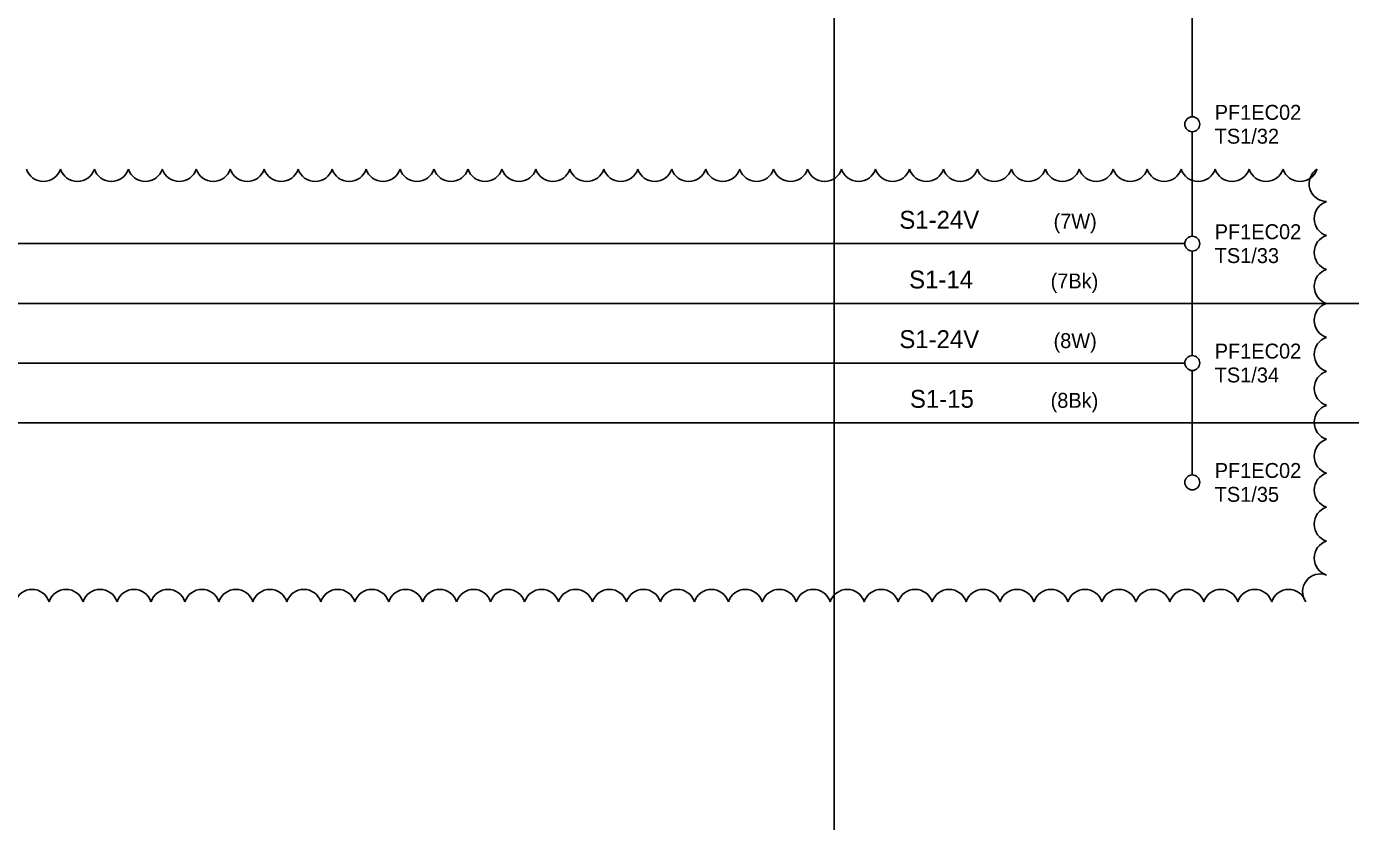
# Model space of a CAD drawing. Extents: x 0 to 841, y 0 to 594.
# Drawn here: x 414.7 to 636.5, y 133.2 to 266.4 of the extents above; entities that cross this region are included whole.
import ezdxf

# ---------------------------------------------------------------- set-up
doc = ezdxf.new("R2010")
doc.units = 0
for name, color, linetype in [('Level 1', 7, 'Continuous'), ('Level 10', 7, 'Continuous'), ('Level 2', 7, 'Continuous')]:
    doc.layers.add(name, color=color, linetype=linetype)

msp = doc.modelspace()

# ---------------------------------------------------------------- linework, layer by layer
at = {"layer": 'Level 1'}
for p, q in [((550, 572.5), (550, 57)), ((610, 251.25), (610, 268.75)), ((610, 231.25), (610, 248.75)), ((270, 230), (608.75, 230)), ((610, 211.25), (610, 228.75)), ((270, 220), (685, 220)), ((270, 210), (608.75, 210)), ((610, 191.25), (610, 208.75)), ((270, 200), (685, 200))]:
    msp.add_line(p, q, dxfattribs=at)
for centre, start, end in [((417.58, 243.4), 197.5, 342.5), ((423.27, 243.4), 197.5, 342.5), ((428.96, 243.4), 197.5, 342.5), ((434.65, 243.4), 197.5, 342.5), ((440.33, 243.4), 197.5, 342.5), ((446.02, 243.4), 197.5, 342.5), ((451.71, 243.4), 197.5, 342.5), ((457.4, 243.4), 197.5, 342.5), ((463.09, 243.4), 197.5, 342.5), ((468.78, 243.4), 197.5, 342.5), ((474.46, 243.4), 197.5, 342.5), ((480.15, 243.4), 197.5, 342.5), ((485.84, 243.4), 197.5, 342.5), ((491.53, 243.4), 197.5, 342.5), ((497.22, 243.4), 197.5, 342.5), ((502.9, 243.4), 197.5, 342.5), ((508.59, 243.4), 197.5, 342.5), ((514.28, 243.4), 197.5, 342.5), ((519.97, 243.4), 197.5, 342.5), ((525.66, 243.4), 197.5, 342.5), ((531.35, 243.4), 197.5, 342.5), ((537.03, 243.4), 197.5, 342.5), ((542.72, 243.4), 197.5, 342.5), ((548.41, 243.4), 197.5, 342.5), ((554.1, 243.4), 197.5, 342.5), ((559.79, 243.4), 197.5, 342.5), ((565.48, 243.4), 197.5, 342.5), ((571.16, 243.4), 197.5, 342.5), ((576.85, 243.4), 197.5, 342.5), ((582.54, 243.4), 197.5, 342.5), ((588.23, 243.4), 197.5, 342.5), ((593.92, 243.4), 197.5, 342.5), ((599.61, 243.4), 197.5, 342.5), ((605.29, 243.4), 197.5, 342.5), ((610.98, 243.4), 197.5, 342.5), ((616.67, 243.4), 197.5, 342.5), ((622.36, 243.4), 197.5, 342.5), ((628.05, 243.4), 197.5, 342.5), ((632.55, 240.03), 123.9457, 268.9457), ((633.4, 234.2), 107.5, 252.5), ((633.4, 228.52), 107.5, 252.5), ((633.4, 222.83), 107.5, 252.5), ((633.4, 217.14), 107.5, 252.5), ((633.4, 211.45), 107.5, 252.5), ((633.4, 205.76), 107.5, 252.5), ((633.4, 200.07), 107.5, 252.5), ((633.4, 194.39), 107.5, 252.5), ((633.4, 188.7), 107.5, 252.5), ((633.4, 183.01), 107.5, 252.5), ((633.4, 177.32), 107.5, 252.5), ((631.45, 171.69), 69.4277, 214.4277), ((415.68, 169.1), 17.5, 162.5), ((421.37, 169.1), 17.5, 162.5), ((427.06, 169.1), 17.5, 162.5), ((432.75, 169.1), 17.5, 162.5), ((438.44, 169.1), 17.5, 162.5), ((444.12, 169.1), 17.5, 162.5), ((449.81, 169.1), 17.5, 162.5), ((455.5, 169.1), 17.5, 162.5), ((461.19, 169.1), 17.5, 162.5), ((466.88, 169.1), 17.5, 162.5), ((472.57, 169.1), 17.5, 162.5), ((478.25, 169.1), 17.5, 162.5), ((483.94, 169.1), 17.5, 162.5), ((489.63, 169.1), 17.5, 162.5), ((495.32, 169.1), 17.5, 162.5), ((501.01, 169.1), 17.5, 162.5), ((506.7, 169.1), 17.5, 162.5), ((512.38, 169.1), 17.5, 162.5), ((518.07, 169.1), 17.5, 162.5), ((523.76, 169.1), 17.5, 162.5), ((529.45, 169.1), 17.5, 162.5), ((535.14, 169.1), 17.5, 162.5), ((540.82, 169.1), 17.5, 162.5), ((546.51, 169.1), 17.5, 162.5), ((552.2, 169.1), 17.5, 162.5), ((557.89, 169.1), 17.5, 162.5), ((563.58, 169.1), 17.5, 162.5), ((569.27, 169.1), 17.5, 162.5), ((574.95, 169.1), 17.5, 162.5), ((580.64, 169.1), 17.5, 162.5), ((586.33, 169.1), 17.5, 162.5), ((592.02, 169.1), 17.5, 162.5), ((597.71, 169.1), 17.5, 162.5), ((603.4, 169.1), 17.5, 162.5), ((609.08, 169.1), 17.5, 162.5), ((614.77, 169.1), 17.5, 162.5), ((620.46, 169.1), 17.5, 162.5), ((626.15, 169.1), 17.5, 162.5)]:
    msp.add_arc(centre, 2.98, start, end, dxfattribs=at)
at = {"layer": 'Level 10'}
for centre in [(610, 250), (610, 230), (610, 210), (610, 190)]:
    msp.add_circle(centre, 1.25, dxfattribs=at)

# ---------------------------------------------------------------- texts
at = {"layer": 'Level 1'}
for s, height, p in [('S1-24V', 3, (560.93, 232.5)), ('(7W)', 2.5, (586.76, 232.5)), ('S1-14', 3, (562.57, 222.5)), ('(7Bk)', 2.5, (586.27, 222.5)), ('S1-24V', 3, (560.93, 212.5)), ('(8W)', 2.5, (586.76, 212.5)), ('S1-15', 3, (562.71, 202.5)), ('(8Bk)', 2.5, (586.27, 202.5))]:
    msp.add_text(s, height=height, dxfattribs=at).set_placement(p)
at = {"layer": 'Level 2'}
for s, p in [('PF1EC02', (613.75, 250.75)), ('TS1/32', (613.75, 246.75)), ('PF1EC02', (613.75, 230.75)), ('TS1/33', (613.75, 226.75)), ('PF1EC02', (613.75, 210.75)), ('TS1/34', (613.75, 206.75)), ('PF1EC02', (613.75, 190.75)), ('TS1/35', (613.75, 186.75))]:
    msp.add_text(s, height=2.5, dxfattribs=at).set_placement(p)

doc.saveas('drawing.dxf')
